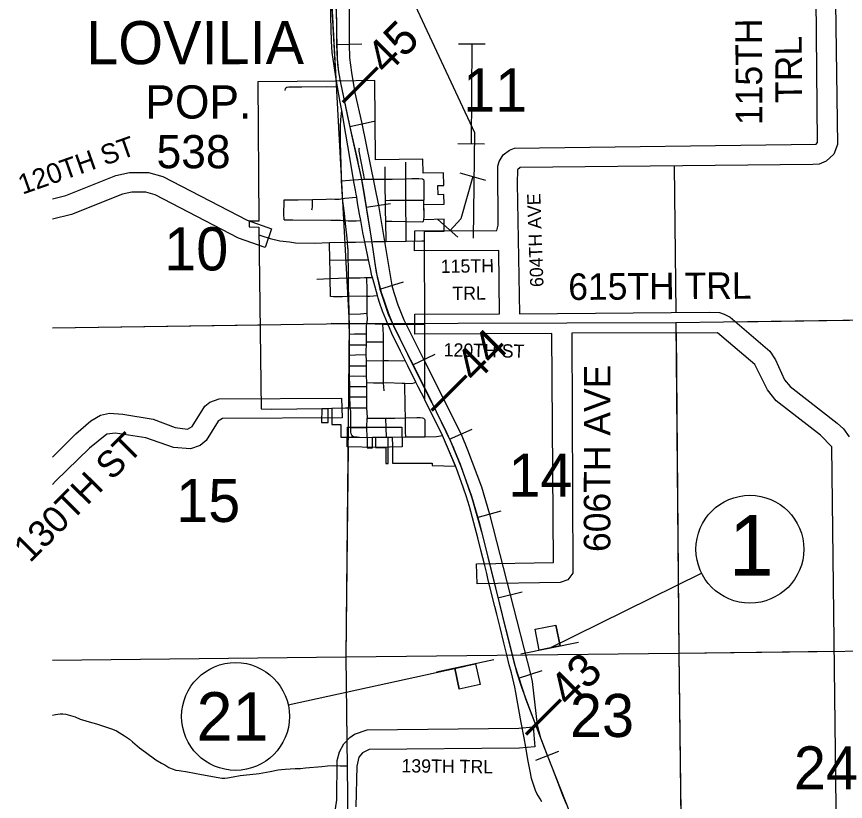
# Model space of a CAD drawing. Extents: x 10133 to 81668, y 5524 to 11018.
# Drawn here: x 14992.6 to 15305, y 9263.3 to 9559.1 of the extents above; entities that cross this region are included whole.
import ezdxf

# ---------------------------------------------------------------- set-up
doc = ezdxf.new("R2010")
doc.units = 0
for name, color, linetype in [('Default', 7, 'Continuous'), ('DisBoundDim', 7, 'Continuous'), ('DisCLMLOR', 7, 'Continuous'), ('DisCLMLSUR', 7, 'Continuous'), ('trf_SignNumber_Text', 7, 'Continuous')]:
    doc.layers.add(name, color=color, linetype=linetype)

msp = doc.modelspace()

# ---------------------------------------------------------------- linework, layer by layer
at = {"layer": 'Default'}
for p, q in [((15113.35, 9548.64), (15122.72, 9548.91)), ((15159.09, 9548.9), (15169.15, 9548.85)), ((15118.15, 9517.73), (15127.31, 9519.74)), ((15158.91, 9511.23), (15168.99, 9511.18)), ((15159.69, 9500.27), (15169.36, 9497.49)), ((15124.27, 9487.25), (15133.54, 9488.67)), ((15151.32, 9482.67), (15158.89, 9475.97)), ((15129.49, 9456.34), (15138.41, 9459.21)), ((15141.94, 9427.83), (15150.37, 9431.94)), ((15155.79, 9399.79), (15164.33, 9403.65)), ((15166.23, 9370.29), (15175.27, 9372.79)), ((15173.97, 9340.08), (15183.08, 9342.29)), ((15181.76, 9309.81), (15190.71, 9312.6)), ((15188.24, 9278.83), (15196.99, 9282.21))]:
    msp.add_line(p, q, dxfattribs=at)
for points in [[(15157.06, 9694.37), (15137.44, 9575.03), (15165.13, 9515.43), (15164.7, 9475.57)], [(15190.5, 9263.2), (15189.86, 9264.22), (15189.26, 9265.27), (15188.71, 9266.34), (15188.21, 9267.44), (15187.75, 9268.55), (15187.34, 9269.69), (15186.98, 9270.84), (15186.67, 9272), (15186.21, 9274.13), (15185.29, 9279.09), (15184.49, 9283.75), (15183.83, 9287.3), (15182.78, 9293.06), (15181.25, 9301.5), (15180.76, 9304.34), (15180.32, 9306.4), (15179.09, 9311.74), (15178.26, 9314.76), (15177.33, 9318.56), (15176.22, 9323.08), (15174.81, 9328.91), (15173.6, 9333.84), (15172.83, 9336.83), (15170.98, 9344.2), (15170.24, 9347.34), (15169.78, 9349.25), (15169.04, 9352.27), (15167.59, 9357.95), (15166.39, 9362.69), (15164.94, 9368.3), (15163.25, 9374.44), (15161.98, 9378.54), (15161.18, 9381.04), (15161.06, 9381.43), (15158.9, 9387.45), (15158.02, 9389.74), (15153.07, 9401.22), (15152.32, 9402.81), (15146.49, 9414.61), (15146.38, 9414.82), (15143.98, 9419.63), (15143.11, 9421.36), (15140.03, 9427.46), (15138.98, 9429.56), (15137.26, 9432.98), (15134.05, 9439.63), (15133.07, 9441.85), (15132.5, 9443.2), (15131.71, 9445.06), (15130.48, 9448.11), (15129.34, 9451.38), (15128.81, 9453.01), (15128.57, 9453.94), (15127.21, 9459.05), (15126.67, 9460.82), (15126.47, 9461.46), (15125.95, 9464.05), (15125.42, 9466.33), (15125.19, 9467.5), (15123.83, 9474.22), (15123.11, 9477.8), (15122.3, 9482.23), (15121.85, 9484.67), (15121.11, 9488.99), (15120.75, 9491.05), (15120.54, 9492.22), (15120.28, 9493.76), (15119.82, 9496.27), (15119.59, 9497.57), (15118.15, 9506.03), (15116.67, 9514.79), (15115.12, 9523.75), (15114.57, 9526.93), (15113.56, 9532.7), (15113.19, 9534.81), (15112.26, 9540.59), (15111.83, 9543.12), (15111.46, 9545.55), (15111.21, 9549.9), (15111.06, 9559.05), (15111.09, 9566.67)], [(15111.08, 9568.24), (15117.95, 9443.49)], [(15201.14, 9259.29), (15192.64, 9280.57), (15184.62, 9301.58), (15180.36, 9314.76), (15175.9, 9332.97), (15171.91, 9348.96), (15167.22, 9367.97), (15164.12, 9378.29), (15160.26, 9389.16), (15156.24, 9399), (15147.3, 9417.48), (15135.03, 9441.81), (15132.83, 9447.07), (15130.2, 9454.7), (15128.28, 9462.65), (15126.35, 9475.67), (15122.69, 9497.72), (15118.88, 9514.52), (15114.86, 9533.54), (15114.06, 9538.33), (15113.55, 9542.98), (15113.23, 9548.58), (15113.09, 9569.21)], [(15361.12, 9566.75), (15302.29, 9566.34), (15301.55, 9565.91), (15301.29, 9564.37), (15301.93, 9510.93), (15300.65, 9507.31), (15297.74, 9504.66), (15295.03, 9503.54), (15292.63, 9503.35), (15182.35, 9502.29), (15181.33, 9501.38), (15181.2, 9496.37), (15182.08, 9447.13), (15253.56, 9447.66), (15257.46, 9447.55), (15259.31, 9447.01), (15261.5, 9445.81), (15276.42, 9432.96), (15278.59, 9429.74), (15282, 9422.24), (15284.16, 9419.65), (15301.86, 9405.94), (15304.21, 9403.72), (15306.35, 9400.78)], [(15111.28, 9564.51), (15112.92, 9534.81)], [(15112.94, 9563.56), (15113.1, 9556.38), (15113.12, 9552.82), (15113.37, 9544.13), (15113.52, 9541.04), (15113.92, 9538.28), (15114.5, 9534.83), (15117.34, 9521.49), (15118.69, 9515.29), (15121, 9505.04), (15121.3, 9503.46), (15122.51, 9497.91), (15123.46, 9492.97), (15124.35, 9487.46), (15124.37, 9487.32), (15125.8, 9477.98), (15127.3, 9467.96), (15127.73, 9465.13), (15128.64, 9460.33), (15128.71, 9460), (15129.51, 9456.42), (15131.7, 9449.61), (15132.65, 9447), (15134.08, 9443.64), (15139.88, 9431.89), (15142.67, 9426.19), (15146.48, 9418.74), (15149.05, 9413.48), (15149.98, 9411.76), (15154, 9403.77), (15157.22, 9396.64), (15157.68, 9395.55), (15159.8, 9390.47), (15162.75, 9381.78), (15164.18, 9377.7), (15165.82, 9371.99), (15167.79, 9364.88), (15170.2, 9355.4), (15171.87, 9348.76), (15172.87, 9344.81), (15175.58, 9333.66), (15176.98, 9328.1), (15179.46, 9318.22), (15180.93, 9312.57), (15182.87, 9306.34), (15184.24, 9302.6), (15186.5, 9296.55), (15190.01, 9287.31), (15191.15, 9284.31), (15194.38, 9275.96), (15197.04, 9269.01), (15199.73, 9262.37)], [(15117.87, 9563.35), (15117.93, 9548.72), (15118.08, 9543.61), (15118.77, 9538.06), (15120.1, 9530.43), (15122.72, 9518.81), (15129, 9487.89), (15134.01, 9457.79), (15134.7, 9455.1), (15136.27, 9450.53), (15138.58, 9444.87), (15146.11, 9429.8), (15160.09, 9401.72), (15162.5, 9395.88), (15167.79, 9381.92), (15170.79, 9371.61), (15178.56, 9341.19), (15186.26, 9311.22), (15186.94, 9308.52), (15188.83, 9292.1), (15190.01, 9287.31), (15191.15, 9284.31), (15192.77, 9280.14), (15194.38, 9275.96), (15197.04, 9269.01), (15198.39, 9265.69), (15199.73, 9262.37)], [(15301.85, 9229.9), (15299.87, 9396.97), (15295.6, 9401.4), (15278.9, 9414.32), (15275.55, 9418.41), (15270.81, 9427.96), (15256.77, 9439.95), (15201.85, 9439.74), (15202.19, 9349.31), (15200.37, 9346.86), (15197.4, 9345.87), (15166.19, 9345.34), (15165.87, 9352.83), (15194.89, 9353.3), (15194.36, 9439.7), (15142.72, 9439.46), (15142.64, 9446.96), (15174.58, 9447.09), (15174.3, 9470.94), (15142.59, 9470.84), (15142.64, 9478.34), (15173.59, 9478.55), (15174.06, 9480.55), (15173.94, 9502.71), (15174.44, 9504.52), (15175.95, 9506.98), (15178.32, 9508.84), (15180.26, 9509.51), (15293.89, 9511.1), (15294.44, 9511.68), (15293.97, 9566.22)], [(15164.13, 9548.87), (15163.95, 9511.2)], [(15093.82, 9531.24), (15093.98, 9532.01), (15094.1, 9532.32), (15094.44, 9532.53), (15095.15, 9532.62), (15100.02, 9532.59), (15109.54, 9532.73), (15113.56, 9532.7)], [(15117.32, 9474.09), (15117.22, 9475.6), (15117.09, 9476.72), (15116.85, 9478.86), (15116.44, 9482.24), (15116.11, 9485.03), (15115.43, 9490.55), (15115.37, 9491.07), (15115.25, 9493.38), (15115.05, 9497.25), (15114.97, 9498.9), (15114.66, 9511.95), (15114.66, 9517.78), (15114.72, 9520.4), (15115.12, 9523.75)], [(15123.75, 9497.83), (15123.48, 9499.3), (15121.72, 9508.4), (15121.69, 9509.26), (15121.81, 9509.69)], [(15139.27, 9498.01), (15139.29, 9504.23)], [(15131.5, 9497.88), (15131.55, 9502.48)], [(15240.41, 9502.99), (15241.05, 9447.57)], [(15006.1, 9490.48), (15011.14, 9491.65), (15029.92, 9499.28), (15035.17, 9500.41), (15042.33, 9500.4), (15047.65, 9498.91), (15079.46, 9482.42), (15088.6, 9479.19), (15086.2, 9472.08), (15076.2, 9475.67), (15044.8, 9491.96), (15041.23, 9492.98), (15035.97, 9492.96), (15032.48, 9492.23), (15013.29, 9484.47), (15006.1, 9482.81)], [(15115.05, 9497.25), (15119.59, 9497.57), (15121.5, 9497.7), (15123.32, 9497.82), (15123.75, 9497.83)], [(15123.75, 9497.83), (15126.5, 9497.88), (15131.5, 9497.88)], [(15131.56, 9489.81), (15131.46, 9494.4), (15131.5, 9497.88)], [(15131.5, 9497.88), (15134.08, 9497.88), (15139.27, 9498.01)], [(15139.28, 9489.9), (15139.26, 9493.11), (15139.27, 9498.01)], [(15139.27, 9498.01), (15141.51, 9498.07), (15144.16, 9498.13), (15145.52, 9498.01), (15145.88, 9497.76), (15145.92, 9497.73), (15146.1, 9497.18), (15146.04, 9492.12), (15146.07, 9489.87)], [(15164.53, 9498.88), (15159.97, 9482.95), (15156.02, 9478.48)], [(15093.38, 9482.47), (15093.34, 9484.78), (15093.35, 9486.47), (15093.36, 9487.76), (15093.39, 9490.05), (15093.86, 9490.06), (15098.72, 9490.06), (15104.06, 9490.19)], [(15103.87, 9486.29), (15104.03, 9486.69), (15104.12, 9487.37), (15104.06, 9490.19)], [(15104.06, 9490.19), (15109.2, 9490.31), (15110.93, 9490.4), (15112.5, 9490.28), (15114.14, 9490.34), (15115.43, 9490.55), (15116.23, 9490.68), (15120.74, 9491.05)], [(15131.56, 9489.81), (15133.19, 9489.87), (15138.46, 9489.9), (15139.28, 9489.9)], [(15131.73, 9482.06), (15131.65, 9485.86), (15131.56, 9489.81)], [(15139.35, 9481.91), (15139.32, 9485.25), (15139.28, 9489.9)], [(15139.28, 9489.9), (15146.07, 9489.87)], [(15139.35, 9481.91), (15145.61, 9481.76), (15145.86, 9481.92), (15145.95, 9481.98), (15146.1, 9482.53), (15146.16, 9483.83), (15146.07, 9489.87)], [(15093.38, 9482.47), (15093.95, 9482.5), (15096.63, 9482.56), (15111.05, 9482.45), (15114.69, 9482.39), (15116.44, 9482.24), (15117.53, 9482.14), (15120.52, 9482.14), (15122.29, 9482.23)], [(15131.89, 9474.37), (15131.73, 9482.06)], [(15131.73, 9482.06), (15134.05, 9482.04), (15139.35, 9481.91)], [(15139.44, 9474.49), (15139.38, 9477.01), (15139.35, 9481.91)], [(15083.87, 9476.82), (15085.03, 9476.45), (15088.18, 9475.44), (15091.73, 9474.64), (15095.37, 9474.21), (15097.71, 9473.9), (15104.89, 9473.77), (15110.49, 9473.95), (15110.69, 9473.96), (15117.32, 9474.09)], [(15110.65, 9467.35), (15110.49, 9473.95)], [(15117.32, 9474.09), (15120.34, 9474.14), (15123.83, 9474.22), (15127.15, 9474.3), (15131.89, 9474.37), (15139.44, 9474.49), (15145.31, 9474.58), (15146.36, 9474.57)], [(15117.94, 9443.48), (15117.93, 9444.62), (15117.88, 9446.97), (15117.74, 9453.57), (15117.74, 9453.59), (15117.71, 9457.06), (15117.67, 9460.61), (15117.62, 9465.12), (15117.57, 9467.45), (15117.5, 9471.47), (15117.47, 9471.82), (15117.32, 9474.09)], [(15110.65, 9467.35), (15117.57, 9467.45), (15119.25, 9467.47), (15120.35, 9467.45), (15122.92, 9467.41), (15125.18, 9467.5)], [(15110.78, 9460.39), (15110.75, 9463.05), (15110.65, 9467.35)], [(15105.78, 9460.21), (15110.78, 9460.39)], [(15110.78, 9460.39), (15113.92, 9460.5), (15117.67, 9460.61), (15119.47, 9460.66), (15122.02, 9460.71), (15123.66, 9460.75), (15124.59, 9460.77)], [(15124.69, 9453.78), (15117.74, 9453.57), (15117.74, 9453.57), (15115.4, 9453.49), (15111.98, 9453.49), (15110.93, 9453.59), (15110.87, 9454.05), (15110.78, 9460.39)], [(15124.59, 9460.77), (15126.66, 9460.81)], [(15124.69, 9453.78), (15124.68, 9455.96), (15124.59, 9460.77)], [(15124.69, 9453.78), (15125.6, 9453.81), (15128.56, 9453.94)], [(15124.76, 9447.29), (15124.71, 9450.78), (15124.69, 9453.78)], [(15117.88, 9446.97), (15122.21, 9447.14), (15124.76, 9447.29)], [(15124.49, 9439.56), (15124.49, 9442.49), (15124.62, 9443.39), (15124.8, 9444.77), (15124.76, 9447.29)], [(15241.09, 9443.81), (15366.76, 9445.52)], [(15263.5, 9444.12), (15366.76, 9445.52)], [(15006.1, 9441.87), (15117.95, 9443.49)], [(15006.1, 9441.87), (15084.32, 9443)], [(15111.12, 9443.51), (15117.94, 9443.48)], [(15117.95, 9443.49), (15116.72, 9317.83)], [(15120.98, 9400.57), (15120.24, 9400.6), (15119.59, 9400.75), (15119.19, 9401.03), (15118.88, 9401.4), (15118.7, 9401.89), (15118.54, 9402.6), (15118.57, 9404.25), (15118.58, 9404.67), (15118.51, 9410.37), (15118.36, 9411.64), (15118.27, 9412.43), (15118.15, 9415.81), (15118.11, 9416.94), (15118.11, 9419.66), (15118.1, 9423.59), (15118.09, 9427.5), (15118.08, 9431.51), (15118.08, 9432.16), (15118.04, 9435.4), (15117.99, 9439.44), (15117.94, 9443.48)], [(15117.94, 9443.48), (15120.46, 9443.48), (15124.62, 9443.39), (15127.67, 9443.32), (15130.67, 9443.24), (15131.95, 9443.2), (15132.49, 9443.2), (15136.55, 9443.17), (15144.53, 9443.23), (15146.43, 9443.25)], [(15117.95, 9443.49), (15241.09, 9443.81)], [(15130.87, 9429.49), (15130.87, 9431.61), (15130.83, 9436.52), (15130.81, 9439.16), (15130.67, 9443.24)], [(15241.09, 9443.81), (15242.24, 9319.19)], [(15117.99, 9439.44), (15119.99, 9439.56), (15124.49, 9439.56)], [(15124.44, 9436.51), (15124.49, 9439.22), (15124.49, 9439.56)], [(15241.12, 9440.06), (15242.24, 9319.19)], [(15118.04, 9435.4), (15124.42, 9435.37)], [(15124.39, 9431.7), (15124.37, 9433.15), (15124.42, 9435.37)], [(15124.42, 9435.37), (15124.44, 9436.51)], [(15124.44, 9436.51), (15126.81, 9436.51), (15129.49, 9436.54), (15130.83, 9436.52)], [(15118.08, 9431.51), (15120.3, 9431.61), (15124.39, 9431.7)], [(15124.42, 9429.4), (15124.39, 9431.7)], [(15124.42, 9429.4), (15130.87, 9429.49)], [(15124.45, 9427.55), (15124.42, 9429.4)], [(15130.92, 9421.14), (15130.84, 9422.73), (15130.87, 9429.49)], [(15130.87, 9429.49), (15132.75, 9429.52), (15138, 9429.34), (15138.97, 9429.56)], [(15118.09, 9427.5), (15120.18, 9427.48), (15124.45, 9427.55)], [(15124.5, 9423.68), (15124.45, 9427.55)], [(15118.1, 9423.59), (15119.44, 9423.66), (15123.51, 9423.62), (15124.5, 9423.68)], [(15124.54, 9421.15), (15124.5, 9423.68)], [(15118.11, 9419.66), (15120.09, 9419.68), (15124.56, 9419.73)], [(15124.56, 9419.73), (15124.56, 9419.8), (15124.54, 9421.15)], [(15124.54, 9421.15), (15127.11, 9421.07), (15130.92, 9421.14)], [(15124.57, 9415.78), (15124.56, 9419.73)], [(15130.92, 9421.14), (15132.02, 9421.16), (15137.84, 9420.95), (15138.87, 9420.93)], [(15131.06, 9418.04), (15130.92, 9421.14)], [(15138.87, 9420.93), (15141.23, 9420.89), (15142.37, 9421.04), (15143.1, 9421.36)], [(15139.12, 9407.87), (15139.07, 9412.19), (15138.87, 9420.93)], [(15006.1, 9393.03), (15014.9, 9401.88), (15020.53, 9406.71), (15024.2, 9408.85), (15027.53, 9409.66), (15032.66, 9409.33), (15043.98, 9407.42), (15052.38, 9404.29), (15056.94, 9403.66), (15058.75, 9404.58), (15063.5, 9412.24), (15065.41, 9413.85), (15068.94, 9415.04), (15115.03, 9415.35), (15115.27, 9407.86), (15070.2, 9407.64), (15068.59, 9406.64), (15064.08, 9399.3), (15061.7, 9397.47), (15058.13, 9396.24), (15051.66, 9396.69), (15041.26, 9400.33), (15029.9, 9402.15), (15026.62, 9401.71), (15020.07, 9396.44), (15007.28, 9383.99), (15006.1, 9382.73)], [(15118.15, 9415.81), (15121.04, 9415.76), (15124.57, 9415.78)], [(15124.76, 9407.75), (15124.77, 9408.03), (15124.63, 9411.64), (15124.59, 9412.74), (15124.57, 9415.78)], [(15107.56, 9411.37), (15110, 9411.44)], [(15110, 9411.44), (15110.01, 9411.44), (15111.4, 9411.48), (15111.4, 9411.48)], [(15111.4, 9411.48), (15116.53, 9411.64), (15118.36, 9411.64)], [(15118.36, 9411.64), (15124.63, 9411.64)], [(15124.64, 9404.2), (15124.76, 9407.75)], [(15124.76, 9407.75), (15127.33, 9407.75), (15131.8, 9407.77)], [(15131.8, 9407.77), (15135.19, 9407.78), (15139.12, 9407.87)], [(15131.94, 9400.59), (15131.92, 9404.2), (15131.8, 9407.77)], [(15139.12, 9407.87), (15143.39, 9407.96), (15144.65, 9408.06), (15145.55, 9407.93), (15145.88, 9407.77), (15145.98, 9407.72), (15146.29, 9407.44), (15146.38, 9407.07), (15146.49, 9400.76)], [(15139.29, 9400.67), (15139.17, 9402.51), (15139.12, 9407.87)], [(15128.38, 9396.75), (15117.12, 9396.93), (15117.35, 9404.43), (15137.82, 9404.41), (15137.91, 9396.91), (15128.38, 9396.75)], [(15118.57, 9404.25), (15124.64, 9404.2), (15124.64, 9404.2)], [(15124.66, 9400.52), (15124.64, 9404.2)], [(15134.12, 9400.61), (15134.15, 9400.61), (15134.16, 9400.61), (15139.29, 9400.67), (15146.49, 9400.76), (15150.88, 9400.81), (15153.07, 9401.22)], [(15120.98, 9400.57), (15121.85, 9400.54), (15124.66, 9400.52)], [(15124.66, 9400.52), (15126.67, 9400.54)], [(15126.67, 9400.54), (15126.69, 9400.54), (15126.69, 9400.54), (15126.7, 9400.54), (15127.84, 9400.55)], [(15127.84, 9400.55), (15127.88, 9400.55), (15131.59, 9400.59)], [(15131.59, 9400.59), (15131.61, 9400.59), (15131.63, 9400.59), (15131.94, 9400.59), (15132.88, 9400.6), (15134.12, 9400.61)], [(15117.49, 9396.93), (15116.72, 9317.83)], [(15242.24, 9319.19), (15367.42, 9320.74)], [(15242.24, 9319.19), (15300.6, 9319.91)], [(15006.1, 9316.54), (15116.72, 9317.83)], [(15006.1, 9316.54), (15116.72, 9317.83)], [(15116.72, 9317.83), (15242.24, 9319.19)], [(15116.72, 9317.83), (15242.24, 9319.19)], [(15116.72, 9317.83), (15117.09, 9286.41)], [(15116.72, 9317.83), (15118.18, 9192.67)], [(15242.24, 9319.19), (15243.29, 9228.96)], [(15242.24, 9319.19), (15243.7, 9193.61)], [(15006.1, 9295.85), (15007.29, 9296.03), (15008.95, 9296.28), (15010.02, 9296.27), (15011.13, 9296.21), (15012.03, 9295.99), (15014.62, 9295.13), (15016.5, 9294.36), (15018.68, 9293.65), (15019.89, 9293.34), (15022.63, 9292.54), (15026.42, 9291.34), (15028.67, 9290.57), (15030.21, 9289.92), (15033.2, 9288.07), (15035.12, 9286.75), (15036.19, 9285.82), (15038.91, 9283.54), (15041.16, 9281.88), (15045.1, 9278.98), (15047.17, 9277.78), (15048.4, 9277.07), (15049.97, 9276.11), (15051.18, 9275.56), (15052.53, 9275.1), (15053.8, 9274.91), (15057, 9274.42), (15062.24, 9273.46), (15068.56, 9272.32), (15069.95, 9272.1), (15071, 9272.1), (15072.11, 9272.23), (15074.23, 9272.54), (15076.82, 9273.06), (15080.46, 9273.4), (15083.94, 9273.86), (15088.1, 9274.54), (15091.16, 9275.19), (15092.39, 9275.34), (15093.75, 9275.46), (15097.57, 9275.68), (15099.6, 9275.74), (15101.42, 9275.96), (15107.65, 9276.48), (15109.71, 9276.67), (15112.12, 9276.79), (15114.49, 9276.73), (15115.79, 9276.7), (15117.01, 9276.7)], [(15102.46, 9190.56), (15113.23, 9263.88), (15113.39, 9278.79), (15114.27, 9282.04), (15115.92, 9284.99), (15118.15, 9287.45), (15119.99, 9288.69), (15124.66, 9290.3), (15181.85, 9290.88), (15187.22, 9291.38), (15187.91, 9283.91), (15182.1, 9283.39), (15125.51, 9282.84), (15122.94, 9281.66), (15121.55, 9279.94), (15120.76, 9276.61), (15120.45, 9261.26)]]:
    msp.add_lwpolyline(points, dxfattribs=at)
msp.add_lwpolyline([(15127.55, 9535.09), (15113.19, 9534.81), (15083.54, 9534.58), (15083.81, 9482.02), (15080.17, 9481.99), (15080.18, 9479.83), (15083.81, 9479.76), (15084.75, 9411.25), (15088.76, 9411.21), (15107.56, 9411.37), (15107.53, 9406.07), (15110.01, 9406.14), (15110.01, 9411.44), (15111.4, 9411.48), (15111.4, 9405.33), (15114.79, 9405.35), (15114.84, 9400.55), (15120.98, 9400.57), (15121.85, 9400.54), (15124.66, 9400.52), (15124.68, 9396.56), (15126.66, 9396.64), (15126.7, 9400.54), (15127.88, 9400.55), (15127.88, 9396.73), (15131.77, 9396.73), (15131.75, 9390.67), (15132.67, 9390.69), (15132.65, 9400.6), (15134.12, 9400.61), (15134.16, 9400.61), (15134.23, 9397.18), (15134.31, 9390.75), (15149.23, 9390.85), (15149.24, 9389.91), (15158.02, 9389.73), (15153.07, 9401.22), (15152.31, 9402.8), (15146.48, 9414.61), (15146.43, 9443.25), (15146.36, 9474.57), (15146.36, 9474.74), (15146.3, 9478.09), (15153.79, 9478.25), (15153.74, 9482.75), (15146.1, 9482.53), (15146.16, 9483.83), (15146.1, 9488.26), (15153.73, 9488.42), (15153.66, 9492.06), (15151.42, 9491.99), (15151.33, 9495.44), (15153.56, 9495.43), (15153.52, 9500.2), (15145.77, 9500.15), (15145.73, 9505.4), (15127.88, 9505.12)], close=True, dxfattribs=at)
at = {"layer": 'DisBoundDim'}
for p, q in [((15187.98, 9328.18), (15195.83, 9329.74)), ((15197.39, 9321.9), (15195.83, 9329.74)), ((15189.55, 9320.33), (15187.98, 9328.18)), ((15182.62, 9318.95), (15204.32, 9323.28)), ((15172.46, 9316.68), (15150.82, 9311.99)), ((15157.73, 9313.49), (15159.43, 9305.67)), ((15165.55, 9315.18), (15167.24, 9307.36)), ((15167.24, 9307.36), (15159.43, 9305.67))]:
    msp.add_line(p, q, dxfattribs=at)
at = {"layer": 'DisCLMLOR'}
for p, q in [((15187.98, 9328.18), (15195.83, 9329.74)), ((15187.98, 9328.18), (15195.83, 9329.74)), ((15187.98, 9328.18), (15195.83, 9329.74)), ((15187.98, 9328.18), (15195.83, 9329.74)), ((15195.83, 9329.74), (15197.39, 9321.9)), ((15195.83, 9329.74), (15197.39, 9321.9)), ((15195.83, 9329.74), (15197.39, 9321.9)), ((15195.83, 9329.74), (15197.39, 9321.9)), ((15189.55, 9320.33), (15187.98, 9328.18)), ((15189.55, 9320.33), (15187.98, 9328.18)), ((15189.55, 9320.33), (15187.98, 9328.18)), ((15189.55, 9320.33), (15187.98, 9328.18)), ((15197.39, 9321.9), (15189.55, 9320.33)), ((15197.39, 9321.9), (15189.55, 9320.33)), ((15197.39, 9321.9), (15189.55, 9320.33)), ((15197.39, 9321.9), (15189.55, 9320.33)), ((15157.73, 9313.49), (15165.55, 9315.18)), ((15157.73, 9313.49), (15165.55, 9315.18)), ((15157.73, 9313.49), (15165.55, 9315.18)), ((15157.73, 9313.49), (15165.55, 9315.18)), ((15159.43, 9305.67), (15157.73, 9313.49)), ((15159.43, 9305.67), (15157.73, 9313.49)), ((15159.43, 9305.67), (15157.73, 9313.49)), ((15159.43, 9305.67), (15157.73, 9313.49)), ((15165.55, 9315.18), (15167.24, 9307.36)), ((15165.55, 9315.18), (15167.24, 9307.36)), ((15165.55, 9315.18), (15167.24, 9307.36)), ((15165.55, 9315.18), (15167.24, 9307.36)), ((15167.24, 9307.36), (15159.43, 9305.67)), ((15167.24, 9307.36), (15159.43, 9305.67)), ((15167.24, 9307.36), (15159.43, 9305.67)), ((15167.24, 9307.36), (15159.43, 9305.67))]:
    msp.add_line(p, q, dxfattribs=at)
at = {"layer": 'DisCLMLSUR'}
for p, q in [((15193.47, 9321.11), (15250.73, 9349.37)), ((15094.95, 9299.68), (15161.64, 9314.33))]:
    msp.add_line(p, q, dxfattribs=at)
at = {"layer": 'trf_SignNumber_Text'}
for centre in [(15268.96, 9358.36), (15075.09, 9295.32)]:
    msp.add_circle(centre, 20.33, dxfattribs=at)

# ---------------------------------------------------------------- texts
at = {"layer": 'Default'}
for s, height, rotation, p in [('LOVILIA', 16.25, 0.024, (15018.79, 9541.17)), ('‒‒45', 12.5, 45, (15118.81, 9523.55)), ('‒‒45', 12.5, 45, (15118.81, 9523.55)), ('115TH', 10, 90.2354, (15273.65, 9518.26)), ('TRL', 10, 90.2354, (15288.62, 9526.58)), ('11', 16.25, 0.0247, (15160.89, 9523.33)), ('120TH ST', 7.5, 19.4333, (14994.78, 9491.97)), ('604TH AVE', 5, 92, (15191.19, 9457.27)), ('10', 16.25, 0.024, (15048.19, 9463.46)), ('115TH', 5, 0.7443, (15152.47, 9462.49)), ('615TH TRL', 10, 0.4014, (15200.53, 9452.3)), ('TRL', 5, 0.7443, (15156.84, 9452.3)), ('‒‒44', 12.5, 45, (15152.29, 9407.41)), ('120TH ST', 5, 358.8858, (15153.48, 9431.07)), ('606TH AVE', 10, 89.9521, (15216.35, 9357.31)), ('130TH ST', 10, 45.1484, (14997.59, 9352.91)), ('14', 16.25, 0.0248, (15177.94, 9378.13)), ('15', 16.25, 0.024, (15052.71, 9368.62)), ('‒‒43', 12.5, 45, (15187.81, 9285.27)), ('23', 16.25, 0.0248, (15201.14, 9287.57)), ('24', 16.25, 0.0256, (15285.56, 9267.82)), ('139TH TRL', 5, 359.3266, (15137.6, 9274.27))]:
    msp.add_text(s, height=height, rotation=rotation, dxfattribs=at).set_placement(p)
for s, p in [('POP.', (15041.1, 9520.71)), ('538', (15045.32, 9501.96))]:
    msp.add_text(s, height=12.5, dxfattribs=at).set_placement(p)
at = {"layer": 'trf_SignNumber_Text'}
for s, height, p in [('1', 22.82, (15260.99, 9348.43)), ('21', 18.258, (15060.39, 9286.22))]:
    msp.add_text(s, height=height, dxfattribs=at).set_placement(p)

doc.saveas('drawing.dxf')
